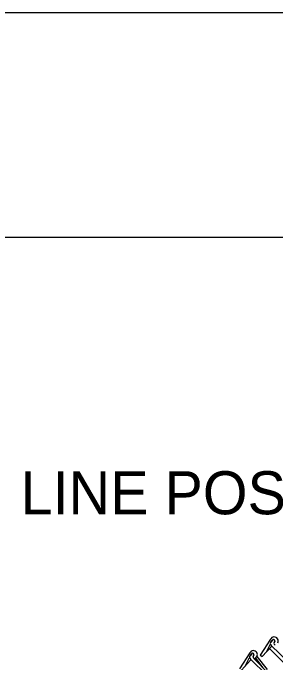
# Model space of a CAD drawing. Extents: x 0 to 2.85, y -0.1 to 1.83.
# Drawn here: x 1.8667 to 1.9276, y 1.6826 to 1.8333 of the extents above; entities that cross this region are included whole.
import ezdxf

# ---------------------------------------------------------------- set-up
doc = ezdxf.new("R2010")
doc.units = 0
for name, color, linetype in [('BDR_Inner_Perimeter', 7, 'Continuous'), ('BDR_Outer_Perimeter', 7, 'Continuous'), ('CT_Dimensions', 7, 'Continuous'), ('sb_Chainlink Fence', 7, 'Continuous')]:
    doc.layers.add(name, color=color, linetype=linetype)

msp = doc.modelspace()

# ---------------------------------------------------------------- linework, layer by layer
at = {"layer": 'BDR_Inner_Perimeter'}
msp.add_lwpolyline([(0.1353943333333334, 1.781248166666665), (2.7812276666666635, 1.781248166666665), (2.7812276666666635, 0.052081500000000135), (0.1353943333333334, 0.052081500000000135)], close=True, dxfattribs=at)
at = {"layer": 'BDR_Outer_Perimeter'}
msp.add_lwpolyline([(0, 0), (2.8333276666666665, 0), (2.833327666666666, 1.8333296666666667), (0, 1.8333296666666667)], close=True, dxfattribs=at)
at = {"layer": 'sb_Chainlink Fence'}
for p, q in [((1.926574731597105, 1.6878670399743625), (1.924182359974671, 1.6841493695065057)), ((1.926630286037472, 1.6871988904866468), (1.9270691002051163, 1.687731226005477)), ((1.9270285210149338, 1.6876874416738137), (1.926630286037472, 1.6871988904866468)), ((1.92755398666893, 1.6874081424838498), (1.9273946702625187, 1.6870519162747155)), ((1.9273951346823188, 1.6870644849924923), (1.9275537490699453, 1.6874001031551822)), ((1.9246319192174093, 1.6838500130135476), (1.9267737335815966, 1.6862130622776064)), ((1.9246319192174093, 1.6838500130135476), (1.9267600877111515, 1.686199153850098)), ((1.926314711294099, 1.6864083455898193), (1.9255216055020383, 1.6848472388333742)), ((1.9263703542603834, 1.6856680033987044), (1.9938262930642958, 1.6182120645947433)), ((1.926816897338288, 1.6863630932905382), (1.9304873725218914, 1.682763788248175)), ((1.9217393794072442, 1.6846883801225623), (1.9193470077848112, 1.680970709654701)), ((1.9217949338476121, 1.6840202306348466), (1.9222337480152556, 1.6845525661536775)), ((1.9221931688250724, 1.6845087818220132), (1.9217949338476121, 1.6840202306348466)), ((1.9227186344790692, 1.6842294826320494), (1.9225593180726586, 1.6838732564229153)), ((1.9225597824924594, 1.6838858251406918), (1.9227183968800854, 1.6842214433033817)), ((1.923437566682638, 1.6839031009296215), (1.9234677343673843, 1.6839763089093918)), ((1.924182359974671, 1.6841493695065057), (1.9246319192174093, 1.6838500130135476)), ((1.91979656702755, 1.680671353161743), (1.9219383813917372, 1.683034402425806)), ((1.91979656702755, 1.680671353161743), (1.9219247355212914, 1.6830204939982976)), ((1.9214793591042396, 1.6832296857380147), (1.920686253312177, 1.6816685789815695)), ((1.9219815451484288, 1.6831844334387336), (1.9256520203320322, 1.6795851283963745)), ((1.9227775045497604, 1.6833364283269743), (1.926043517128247, 1.679948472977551)), ((1.922913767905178, 1.6832425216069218), (1.9234019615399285, 1.6838345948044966)), ((1.922920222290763, 1.6832515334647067), (1.923404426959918, 1.6838366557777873)), ((1.9248552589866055, 1.681192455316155), (1.9231308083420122, 1.683482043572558)), ((1.9234019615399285, 1.6838345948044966), (1.923437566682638, 1.6839031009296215)), ((1.9258981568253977, 1.6808727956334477), (1.9234493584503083, 1.6838785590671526))]:
    msp.add_line(p, q, dxfattribs=at)
for centre, radius, start, end in [((1.9268931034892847, 1.6869187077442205), 0.0003843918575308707, 140.884026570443, 233.68761918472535), ((1.9269036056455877, 1.6869192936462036), 0.0003909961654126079, 134.34955187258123, 232.91672433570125), ((1.9274180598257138, 1.6874622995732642), 0.0009354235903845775, 331.45549705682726, 154.36214988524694), ((1.9272636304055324, 1.6874958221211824), 0.0003033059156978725, 343.19712227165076, 140.81917528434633), ((1.9272647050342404, 1.6874972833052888), 0.0003049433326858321, 341.4167240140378, 129.89976505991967), ((1.9277842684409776, 1.686897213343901), 0.00041880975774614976, 157.16565139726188, 245.8401999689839), ((1.926567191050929, 1.6863672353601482), 0.00025580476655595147, 319.7038284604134, 170.7519254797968), ((1.9220577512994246, 1.68374004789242), 0.0003843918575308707, 140.884026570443, 233.68761918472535), ((1.9220682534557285, 1.6837406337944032), 0.0003909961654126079, 134.34955187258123, 232.91672433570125), ((1.922582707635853, 1.6842836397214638), 0.0009354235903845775, 331.45549705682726, 154.36214988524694), ((1.9224282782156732, 1.684317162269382), 0.0003033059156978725, 343.19712227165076, 140.81917528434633), ((1.9224293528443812, 1.684318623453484), 0.0003049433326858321, 341.4167240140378, 129.89976505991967), ((1.9217318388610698, 1.6831885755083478), 0.00025580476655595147, 319.7038284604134, 170.7519254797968), ((1.9229489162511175, 1.6837185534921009), 0.00041880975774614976, 157.16565139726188, 245.8401999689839)]:
    msp.add_arc(centre, radius, start, end, dxfattribs=at)

# ---------------------------------------------------------------- texts
at = {"layer": 'CT_Dimensions'}
msp.add_text('LINE POST', height=0.01, dxfattribs=at).set_placement((1.8684533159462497, 1.7168900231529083))

doc.saveas('drawing.dxf')
